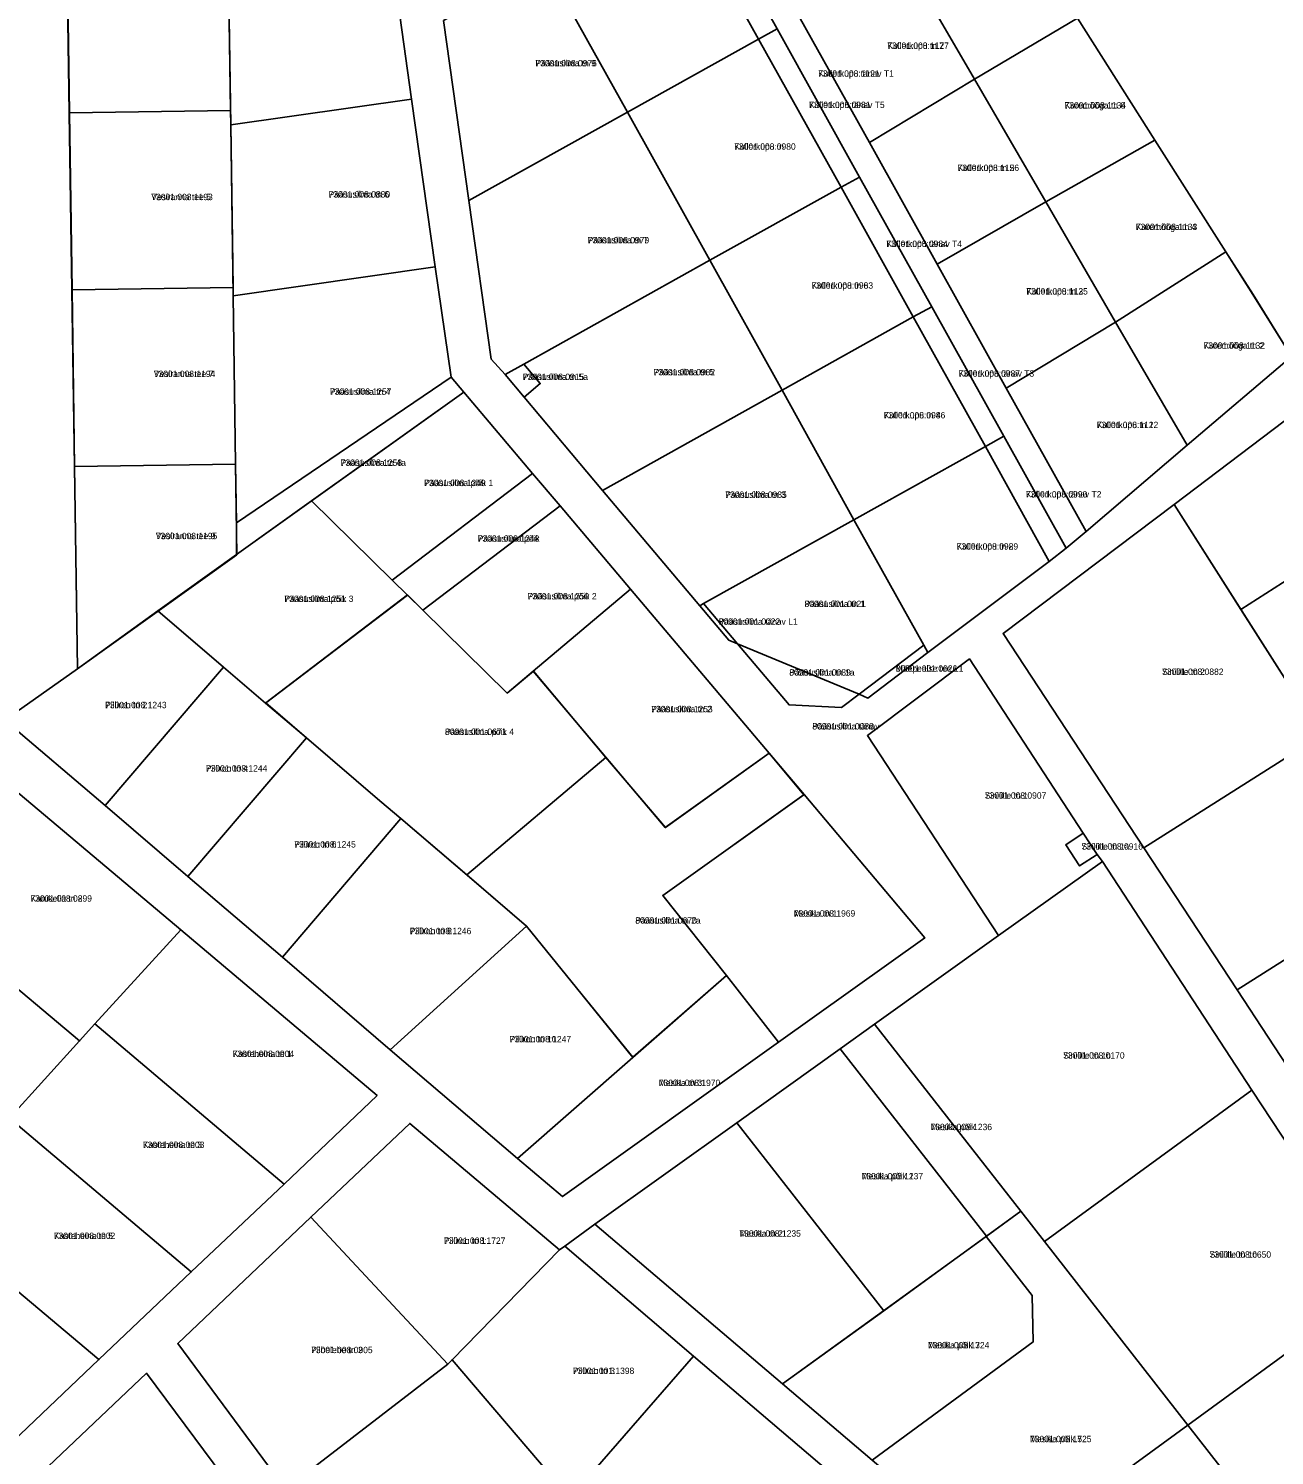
# Model space of a CAD drawing. Extents: x 524000 to 564260, y 6469338 to 6496391.
# Drawn here: x 533230.3 to 533524.2, y 6469655.2 to 6469991.7 of the extents above; entities that cross this region are included whole.
import ezdxf

# ---------------------------------------------------------------- set-up
doc = ezdxf.new("R2010")
doc.units = 0
for name, color, linetype in [('L_AADRESS', 7, 'Continuous'), ('PIIR', 7, 'Continuous'), ('TUNNUS', 7, 'Continuous')]:
    doc.layers.add(name, color=color, linetype=linetype)

msp = doc.modelspace()

# ---------------------------------------------------------------- linework, layer by layer
at = {"layer": 'PIIR'}
for points in [[(533707.29, 6469629.03), (533693.17, 6469654.63), (533679.45, 6469679.69), (533677.05, 6469684.35), (533658.36, 6469709.54), (533656.52, 6469712.46), (533635.06, 6469746.26), (533613.63, 6469780.01), (533592.22, 6469813.75), (533570.65, 6469847.58), (533551.7, 6469877.35), (533534.27, 6469905.02), (533528.24, 6469914.37), (533519.16, 6469929.05), (533512.73, 6469939.07), (533496, 6469965.43), (533477.73, 6469994.16), (533459.77, 6470022.41), (533441.78, 6470050.64), (533423.84, 6470078.86), (533406.93, 6470105.53), (533334.15, 6470219.84), (533366.74, 6470405.16)], [(533014.44, 6470026.6), (533305.84, 6470080.09), (533308.36, 6470062.62), (533273.12, 6470064.08), (533241.2, 6470058.2), (533238.75, 6470055.21), (533239.32, 6470015.09), (533239.95, 6469971.79), (533240.54, 6469930.09), (533241.15, 6469888.38), (533241.88, 6469840.75), (533224.79, 6469828.64)], [(533224.79, 6469828.64), (533248.43, 6469808.5), (533267.91, 6469791.81), (533290.22, 6469772.76), (533315.66, 6469750.9), (533345.68, 6469725.27), (533356.3, 6469716.29), (533407.24, 6469752.7), (533441.72, 6469777.3), (533413.25, 6469811.09), (533405.04, 6469820.84), (533372.33, 6469859.53), (533355.71, 6469879.19), (533349.24, 6469886.82), (533333.01, 6469905.99), (533330.04, 6469909.53), (533326.27, 6469935.55), (533320.68, 6469975.07), (533315.13, 6470014.62)], [(533328.18, 6469993.61), (533334.2, 6469951.16), (533339.48, 6469913.76), (533342.8, 6469910.13), (533347.24, 6469904.84), (533365.71, 6469882.83), (533388.69, 6469855.63), (533395.5, 6469847.51), (533397.57, 6469846.67), (533409.71, 6469832.23), (533422.13, 6469831.63), (533426.27, 6469834.75), (533428.33, 6469833.81), (533442.45, 6469844.57), (533471.1, 6469866.09), (533475.1, 6469869.16), (533479.83, 6469873.1), (533503.63, 6469893.48), (533528.24, 6469914.37)], [(533534.27, 6469905.02), (533500.56, 6469879.53), (533460.2, 6469849.08), (533493.37, 6469798.5), (533515.41, 6469765.02), (533537.34, 6469731.56)], [(533589.38, 6469634.14), (533549.14, 6469695.46), (533518.84, 6469741.37), (533483.62, 6469795.28), (533482.41, 6469796.94), (533479.09, 6469801.97), (533452.26, 6469843.09), (533428.19, 6469824.99), (533459.11, 6469777.85), (533429.89, 6469756.94), (533421.78, 6469751.12), (533397.38, 6469733.71), (533363.95, 6469709.79), (533356.8, 6469704.6), (533355.57, 6469703.73), (533320.24, 6469733.53), (533296.89, 6469711.44), (533265.52, 6469681.64), (533290.95, 6469647.29)], [(533225.03, 6469657.02), (533246.94, 6469677.84), (533268.74, 6469698.54), (533290.6, 6469719.24), (533312.57, 6469740.12), (533266.23, 6469779.2), (533219.32, 6469818.67)], [(533282.99, 6469641.22), (533258.18, 6469674.65), (533207.16, 6469626.35)]]:
    msp.add_lwpolyline(points, dxfattribs=at)
for points in [[(533353.36, 6470087.76), (533364.74, 6470089.93), (533384.06, 6470055.24), (533400.38, 6470025.94), (533412.37, 6469994.1), (533428.68, 6469964.87), (533444.68, 6469936.16), (533460.96, 6469906.92), (533479.83, 6469873.1), (533475.1, 6469869.16), (533460.4, 6469895.57), (533443.37, 6469926.14), (533426.34, 6469956.72), (533406.88, 6469991.66), (533387.42, 6470026.6), (533367.95, 6470061.55)], [(533352.15, 6470006.96), (533361.44, 6470012.13), (533383.05, 6470024.17), (533402.51, 6469989.23), (533371.61, 6469972.02)], [(533387.42, 6470026.6), (533406.88, 6469991.66), (533402.51, 6469989.23), (533383.05, 6470024.17)], [(533436.62, 6470008.7), (533459.75, 6470022.42), (533477.72, 6469994.16), (533453.44, 6469979.77)], [(533239.36, 6470015.12), (533277.31, 6470015.64), (533277.41, 6470009.3), (533277.98, 6469972.39), (533240, 6469971.82)], [(533277.41, 6470009.3), (533315.13, 6470014.62), (533320.68, 6469975.07), (533278.03, 6469969.02)], [(533328.18, 6469993.61), (533352.15, 6470006.96), (533371.61, 6469972.02), (533334.2, 6469951.16)], [(533412.37, 6469994.1), (533436.62, 6470008.7), (533453.44, 6469979.77), (533428.68, 6469964.87)], [(533453.44, 6469979.77), (533477.72, 6469994.16), (533495.99, 6469965.42), (533470.26, 6469950.84)], [(533406.88, 6469991.66), (533426.34, 6469956.72), (533421.98, 6469954.29), (533402.51, 6469989.23)], [(533371.61, 6469972.02), (533402.51, 6469989.23), (533421.98, 6469954.29), (533391.07, 6469937.07)], [(533428.68, 6469964.87), (533453.44, 6469979.77), (533470.26, 6469950.84), (533444.68, 6469936.16)], [(533278.03, 6469969.02), (533320.68, 6469975.07), (533326.27, 6469935.55), (533278.62, 6469928.7)], [(533240, 6469971.82), (533277.98, 6469972.39), (533278.03, 6469969.02), (533278.59, 6469930.68), (533240.6, 6469930.13)], [(533342.8, 6469910.13), (533339.48, 6469913.76), (533334.2, 6469951.16), (533371.61, 6469972.02), (533391.07, 6469937.07), (533347.15, 6469912.61)], [(533470.26, 6469950.84), (533495.99, 6469965.42), (533512.75, 6469939.08), (533486.73, 6469922.5)], [(533426.34, 6469956.72), (533443.37, 6469926.14), (533439.01, 6469923.71), (533421.98, 6469954.29)], [(533391.07, 6469937.07), (533421.98, 6469954.29), (533439.01, 6469923.71), (533408.09, 6469906.49)], [(533444.68, 6469936.16), (533470.26, 6469950.84), (533486.73, 6469922.5), (533460.96, 6469906.92)], [(533347.24, 6469904.84), (533351.03, 6469908.01), (533347.15, 6469912.61), (533391.07, 6469937.07), (533408.09, 6469906.49), (533365.71, 6469882.83)], [(533486.73, 6469922.5), (533512.75, 6469939.08), (533519.13, 6469929.04), (533528.24, 6469914.37), (533503.63, 6469893.48)], [(533278.62, 6469928.7), (533326.27, 6469935.55), (533330.04, 6469909.53), (533279.39, 6469875.17), (533279.19, 6469888.97)], [(533240.6, 6469930.13), (533278.59, 6469930.68), (533278.62, 6469928.7), (533279.19, 6469888.97), (533241.21, 6469888.42)], [(533443.37, 6469926.14), (533460.4, 6469895.57), (533456.04, 6469893.15), (533439.01, 6469923.71)], [(533408.09, 6469906.49), (533439.01, 6469923.71), (533456.04, 6469893.15), (533425.03, 6469875.87)], [(533460.96, 6469906.92), (533486.73, 6469922.5), (533503.63, 6469893.48), (533479.83, 6469873.1)], [(533347.15, 6469912.61), (533351.03, 6469908.01), (533347.24, 6469904.84), (533342.8, 6469910.13)], [(533330.04, 6469909.53), (533333.01, 6469905.99), (533279.42, 6469867.69), (533279.39, 6469875.17)], [(533333.01, 6469905.99), (533349.24, 6469886.82), (533316.14, 6469861.67), (533297.12, 6469880.34)], [(533365.71, 6469882.83), (533408.09, 6469906.49), (533425.03, 6469875.87), (533389.58, 6469856.13), (533388.69, 6469855.63)], [(533534.27, 6469905.02), (533551.7, 6469877.35), (533516.26, 6469854.77), (533500.56, 6469879.53)], [(533456.04, 6469893.15), (533471.1, 6469866.09), (533442.45, 6469844.57), (533441.48, 6469846.32), (533425.03, 6469875.87)], [(533460.4, 6469895.57), (533475.1, 6469869.16), (533471.1, 6469866.09), (533456.04, 6469893.15)], [(533241.21, 6469888.42), (533279.19, 6469888.97), (533279.51, 6469867.65), (533241.9, 6469840.73)], [(533349.24, 6469886.82), (533355.71, 6469879.19), (533323.35, 6469854.59), (533319.74, 6469858.13), (533316.14, 6469861.67)], [(533297.12, 6469880.34), (533316.14, 6469861.67), (533319.74, 6469858.13), (533286.26, 6469832.68), (533276.33, 6469841.17), (533260.84, 6469854.41), (533279.42, 6469867.69)], [(533355.71, 6469879.19), (533372.33, 6469859.53), (533349.38, 6469840.2), (533343.27, 6469835.03), (533323.35, 6469854.59)], [(533460.2, 6469849.08), (533500.56, 6469879.53), (533535.2, 6469825.04), (533493.37, 6469798.5)], [(533389.58, 6469856.13), (533425.03, 6469875.87), (533441.48, 6469846.32), (533426.27, 6469834.75), (533397.57, 6469846.67)], [(533551.7, 6469877.35), (533570.65, 6469847.58), (533535.2, 6469825.04), (533516.26, 6469854.77)], [(533372.33, 6469859.53), (533405.04, 6469820.84), (533380.53, 6469803.33), (533349.38, 6469840.2)], [(533286.29, 6469832.69), (533319.74, 6469858.16), (533323.36, 6469854.6), (533343.26, 6469835.04), (533349.43, 6469840.16), (533366.53, 6469819.86), (533333.71, 6469792.16), (533318.15, 6469805.45), (533313.22, 6469809.64), (533295.87, 6469824.46)], [(533395.5, 6469847.51), (533388.69, 6469855.63), (533389.58, 6469856.13), (533397.57, 6469846.67)], [(533260.84, 6469854.41), (533276.33, 6469841.17), (533248.43, 6469808.5), (533224.79, 6469828.64), (533241.88, 6469840.75)], [(533409.71, 6469832.23), (533397.57, 6469846.67), (533426.27, 6469834.75), (533422.13, 6469831.63)], [(533426.27, 6469834.75), (533441.48, 6469846.32), (533442.45, 6469844.57), (533428.33, 6469833.81)], [(533452.26, 6469843.09), (533479.09, 6469801.97), (533474.97, 6469799.27), (533478.26, 6469794.25), (533482.41, 6469796.94), (533483.62, 6469795.28), (533459.11, 6469777.85), (533428.19, 6469824.99)], [(533276.33, 6469841.17), (533286.26, 6469832.68), (533295.88, 6469824.47), (533267.91, 6469791.81), (533248.43, 6469808.5)], [(533493.37, 6469798.5), (533535.2, 6469825.04), (533556.74, 6469791.26), (533515.41, 6469765.02)], [(533295.88, 6469824.47), (533313.23, 6469809.64), (533318.16, 6469805.44), (533290.22, 6469772.76), (533267.91, 6469791.81)], [(533219.32, 6469818.67), (533266.23, 6469779.2), (533246, 6469756.99), (533242.38, 6469753), (533197.79, 6469790.42)], [(533333.71, 6469792.16), (533366.53, 6469819.86), (533380.57, 6469803.31), (533405.07, 6469820.85), (533413.2, 6469811.04), (533379.95, 6469787.26), (533394.93, 6469768.41), (533372.89, 6469749.14), (533359.59, 6469765.52), (533347.79, 6469780.06)], [(533413.25, 6469811.09), (533441.72, 6469777.3), (533407.24, 6469752.7), (533394.93, 6469768.44), (533379.97, 6469787.3)], [(533318.16, 6469805.44), (533335.42, 6469790.69), (533347.82, 6469780.09), (533315.66, 6469750.9), (533290.22, 6469772.76)], [(533482.41, 6469796.94), (533478.26, 6469794.25), (533474.97, 6469799.27), (533479.09, 6469801.97)], [(533464.4, 6469712.82), (533429.89, 6469756.94), (533459.11, 6469777.85), (533483.62, 6469795.28), (533518.84, 6469741.37), (533469.94, 6469705.73)], [(533197.79, 6469790.42), (533242.38, 6469753), (533225.82, 6469734.76), (533217.27, 6469725.36), (533175.15, 6469760.89)], [(533515.41, 6469765.02), (533556.74, 6469791.26), (533578.18, 6469757.49), (533537.34, 6469731.56)], [(533266.23, 6469779.2), (533312.57, 6469740.12), (533290.6, 6469719.24), (533246, 6469756.99)], [(533347.82, 6469780.09), (533359.6, 6469765.55), (533372.9, 6469749.12), (533345.68, 6469725.27), (533315.66, 6469750.9)], [(533394.93, 6469768.44), (533407.24, 6469752.7), (533356.3, 6469716.29), (533345.68, 6469725.27), (533372.9, 6469749.12)], [(533242.38, 6469753), (533246, 6469756.99), (533290.6, 6469719.24), (533268.74, 6469698.54), (533225.82, 6469734.76)], [(533421.78, 6469751.12), (533429.89, 6469756.94), (533464.4, 6469712.82), (533456.3, 6469706.95)], [(533397.38, 6469733.71), (533421.78, 6469751.12), (533456.3, 6469706.95), (533432.07, 6469689.39)], [(533469.94, 6469705.73), (533518.84, 6469741.37), (533549.14, 6469695.46), (533503.79, 6469662.4)], [(533217.27, 6469725.36), (533225.82, 6469734.76), (533268.74, 6469698.54), (533246.94, 6469677.84), (533205.64, 6469712.54)], [(533296.89, 6469711.44), (533320.24, 6469733.53), (533355.57, 6469703.73), (533330.24, 6469677.82), (533329.22, 6469676.77)], [(533363.95, 6469709.79), (533397.38, 6469733.71), (533432.07, 6469689.39), (533408.2, 6469672.11)], [(533190.57, 6469695.94), (533205.64, 6469712.54), (533246.94, 6469677.84), (533225.03, 6469657.02), (533185.51, 6469690.31)], [(533329.22, 6469676.77), (533290.95, 6469647.29), (533265.52, 6469681.64), (533296.89, 6469711.44)], [(533464.4, 6469712.82), (533469.94, 6469705.73), (533503.79, 6469662.4), (533458.44, 6469629.32), (533429.33, 6469654.12), (533467.27, 6469682.04), (533467.05, 6469693), (533456.21, 6469706.88)], [(533363.95, 6469709.79), (533408.2, 6469672.11), (533429.33, 6469654.12), (533458.44, 6469629.32), (533489.4, 6469602.78), (533478.23, 6469589.95), (533467.54, 6469599.06), (533467.48, 6469610.28), (533449.56, 6469625.55), (533419.11, 6469651.49), (533387.2, 6469678.69), (533356.8, 6469704.6)], [(533355.57, 6469703.73), (533356.8, 6469704.6), (533387.2, 6469678.69), (533358.21, 6469645.37), (533353.12, 6469651), (533330.24, 6469677.82)], [(533456.21, 6469706.88), (533467.05, 6469693), (533467.27, 6469682.04), (533429.33, 6469654.12), (533408.2, 6469672.11), (533431.96, 6469689.34)], [(533549.14, 6469695.46), (533589.38, 6469634.14), (533546.52, 6469607.58), (533503.79, 6469662.4)], [(533329.22, 6469676.77), (533330.24, 6469677.82), (533353.12, 6469651), (533311.78, 6469619.16), (533290.95, 6469647.29)], [(533387.2, 6469678.69), (533419.11, 6469651.49), (533389.06, 6469616.96), (533376.94, 6469625.16), (533358.21, 6469645.37)], [(533207.16, 6469626.35), (533258.18, 6469674.65), (533282.99, 6469641.22), (533235.4, 6469604.47), (533263.96, 6469582.3), (533244.59, 6469567.5), (533232.1, 6469545.7), (533222, 6469552.17), (533216.94, 6469555.09), (533210.42, 6469560.56), (533199.25, 6469568.12), (533183.11, 6469579.86), (533171.71, 6469588.96), (533162.23, 6469599.43), (533166.03, 6469602.86), (533199.32, 6469632.64)], [(533546.52, 6469607.58), (533552.76, 6469599.75), (533551.49, 6469598.85), (533518.23, 6469578.33), (533489.4, 6469602.78), (533458.44, 6469629.32), (533503.79, 6469662.4)]]:
    msp.add_lwpolyline(points, close=True, dxfattribs=at)

# ---------------------------------------------------------------- texts
at = {"layer": 'L_AADRESS'}
for s, p in [('Kullerkupu tn 7', (533432.9, 6469986.94)), ('Pääsusilma tn 9', (533349.89, 6469982.81)), ('Kullerkupu tänav T1', (533416.59, 6469980.37)), ('Kullerkupu tänav T5', (533414.43, 6469972.98)), ('Kuremõõga tn 6', (533474.71, 6469972.87)), ('Kullerkupu tn 8', (533396.79, 6469963.15)), ('Kullerkupu tn 5', (533449.47, 6469958.14)), ('Vesiranna tee 5', (533259.3, 6469951.26)), ('Pääsusilma tn 6', (533301.12, 6469951.88)), ('Kuremõõga tn 4', (533491.5, 6469944.21)), ('Pääsusilma tn 7', (533362.23, 6469941.07)), ('Kullerkupu tänav T4', (533432.67, 6469940.22)), ('Kullerkupu tn 6', (533415.04, 6469930.39)), ('Kullerkupu tn 3', (533465.7, 6469929.01)), ('Kuremõõga tn 2', (533507.48, 6469916.24)), ('Vesiranna tee 7', (533259.89, 6469909.55)), ('Pääsusilma tn 5a', (533346.91, 6469908.85)), ('Pääsusilma tn 5', (533377.78, 6469909.95)), ('Kullerkupu tänav T3', (533449.7, 6469909.64)), ('Pääsusilma tn 4', (533301.42, 6469905.36)), ('Kullerkupu tn 4', (533432.07, 6469899.79)), ('Kullerkupu tn 1', (533482.3, 6469897.51)), ('Pääsusilma tn 4a', (533303.95, 6469888.61)), ('Pääsusilma põik 1', (533323.65, 6469883.83)), ('Pääsusilma tn 3', (533394.68, 6469881.06)), ('Kullerkupu tänav T2', (533465.57, 6469881.15)), ('Vesiranna tee 9', (533260.36, 6469871.32)), ('Pääsusilma põik', (533336.29, 6469870.71)), ('Kullerkupu tn 2', (533449.25, 6469868.86)), ('Pääsusilma põik 2', (533348.06, 6469857.11)), ('Pääsusilma põik 3', (533290.69, 6469856.51)), ('Pääsusilma tn 1', (533413.37, 6469855.31)), ('Pääsusilma tänav L1', (533393.13, 6469851.13)), ('Pääsusilma tn 1a', (533409.78, 6469839.15)), ('Mäepealse tee L1', (533434.9, 6469840.07)), ('Sinilille tn 2', (533497.7, 6469839.31)), ('Pilliroo tn 2', (533248.4, 6469831.46)), ('Pääsusilma tn 2', (533377.21, 6469830.51)), ('Pääsusilma põik 4', (533328.56, 6469825.16)), ('Pääsusilma tänav', (533415.21, 6469826.44)), ('Pilliroo tn 4', (533272.16, 6469816.52)), ('Sinilille tn 1', (533455.9, 6469810.12)), ('Pilliroo tn 6', (533293.03, 6469798.6)), ('Sinilille tn 1a', (533478.69, 6469798.12)), ('Karukella tn 2', (533230.8, 6469785.84)), ('Pääsusilma tn 2a', (533373.46, 6469780.67)), ('Mesika tn 1', (533410.84, 6469782.32)), ('Pilliroo tn 8', (533320.27, 6469778.17)), ('Pilliroo tn 10', (533343.82, 6469752.68)), ('Kasteheina tn 1', (533278.48, 6469749.22)), ('Sinilille tn 1b', (533474.37, 6469748.83)), ('Mesika tn 3', (533378.99, 6469742.37)), ('Mesika põik', (533443.09, 6469731.96)), ('Kasteheina tn 3', (533257.32, 6469727.76)), ('Mesika põik 1', (533426.84, 6469720.36)), ('Kasteheina tn 5', (533236.31, 6469706.3)), ('Mesika tn 2', (533398.01, 6469706.85)), ('Pilliroo tn 1', (533328.32, 6469705.15)), ('Sinilille tn 1c', (533508.92, 6469701.88)), ('Piibelehe tn 2', (533297, 6469679.37)), ('Mesika põik 3', (533442.47, 6469680.5)), ('Pilliroo tn 3', (533358.72, 6469674.46)), ('Mesika põik 5', (533466.56, 6469658.38))]:
    msp.add_text(s, height=1.5, dxfattribs=at).set_placement(p)
at = {"layer": 'TUNNUS'}
for s, p in [('73001:008:1127', (533432.9, 6469986.94)), ('73001:008:0976', (533349.89, 6469982.81)), ('73001:008:1121', (533416.59, 6469980.37)), ('73001:008:0981', (533414.43, 6469972.98)), ('73001:008:1134', (533474.71, 6469972.87)), ('73001:008:0980', (533396.79, 6469963.15)), ('73001:008:1126', (533449.47, 6469958.14)), ('73001:008:0880', (533301.12, 6469951.88)), ('73001:008:1193', (533259.3, 6469951.26)), ('73001:008:1133', (533491.5, 6469944.21)), ('73001:008:0979', (533362.23, 6469941.07)), ('73001:008:0984', (533432.67, 6469940.22)), ('73001:008:0983', (533415.04, 6469930.39)), ('73001:008:1125', (533465.7, 6469929.01)), ('73001:008:1132', (533507.48, 6469916.24)), ('73001:008:1194', (533259.89, 6469909.55)), ('73001:008:0915', (533346.91, 6469908.85)), ('73001:008:0982', (533377.78, 6469909.95)), ('73001:008:0987', (533449.7, 6469909.64)), ('73001:008:1257', (533301.42, 6469905.36)), ('73001:008:0986', (533432.07, 6469899.79)), ('73001:008:1122', (533482.3, 6469897.51)), ('73001:008:1258', (533303.95, 6469888.61)), ('73001:008:1249', (533323.65, 6469883.83)), ('73001:008:0985', (533394.68, 6469881.06)), ('73001:008:0990', (533465.57, 6469881.15)), ('73001:008:1195', (533260.36, 6469871.32)), ('73001:008:1248', (533336.29, 6469870.71)), ('73001:008:0989', (533449.25, 6469868.86)), ('73001:008:1250', (533348.06, 6469857.11)), ('73001:008:1251', (533290.69, 6469856.51)), ('80901:001:0021', (533413.37, 6469855.31)), ('80901:001:0022', (533393.13, 6469851.13)), ('80901:001:0089', (533409.78, 6469839.15)), ('80901:001:0026', (533434.9, 6469840.07)), ('73001:008:0882', (533497.7, 6469839.31)), ('73001:008:1243', (533248.4, 6469831.46)), ('73001:008:1253', (533377.21, 6469830.51)), ('80901:001:0671', (533328.56, 6469825.16)), ('80901:001:0088', (533415.21, 6469826.44)), ('73001:008:1244', (533272.16, 6469816.52)), ('73001:008:0907', (533455.9, 6469810.12)), ('73001:008:1245', (533293.03, 6469798.6)), ('73001:008:0916', (533478.69, 6469798.12)), ('73001:008:0899', (533230.8, 6469785.84)), ('80901:001:0670', (533373.46, 6469780.67)), ('73001:008:1969', (533410.84, 6469782.32)), ('73001:008:1246', (533320.27, 6469778.17)), ('73001:008:1247', (533343.82, 6469752.68)), ('73001:008:0904', (533278.48, 6469749.22)), ('73001:008:0170', (533474.37, 6469748.83)), ('73001:008:1970', (533378.99, 6469742.37)), ('73001:008:1236', (533443.09, 6469731.96)), ('73001:008:0903', (533257.32, 6469727.76)), ('73001:008:1237', (533426.84, 6469720.36)), ('73001:008:0902', (533236.31, 6469706.3)), ('73001:008:1235', (533398.01, 6469706.85)), ('73001:008:1727', (533328.32, 6469705.15)), ('73001:008:0650', (533508.92, 6469701.88)), ('73001:008:0905', (533297, 6469679.37)), ('73001:008:1724', (533442.47, 6469680.5)), ('73001:001:1398', (533358.72, 6469674.46)), ('73001:008:1725', (533466.56, 6469658.38))]:
    msp.add_text(s, height=1.5, dxfattribs=at).set_placement(p)

doc.saveas('drawing.dxf')
